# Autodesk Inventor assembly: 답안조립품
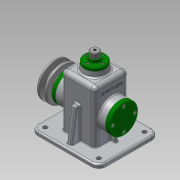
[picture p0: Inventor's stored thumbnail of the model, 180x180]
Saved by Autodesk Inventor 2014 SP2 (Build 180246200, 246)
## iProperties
Created: 2016-08
Part Number: 답안조립품
Document SubType Name: Assembly
Designer: user
Author: user
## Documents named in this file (19)
- C:\Users\user\Desktop\460820V1014\답안조립품.iam
- C:\Users\user\Desktop\460820V1014\본체.ipt
- C:\Users\user\Desktop\460820V1014\뒤커버.ipt
- C:\Users\user\Desktop\460820V1014\앞커버.ipt
- C:\Users\user\Desktop\460820V1014\상부부시.ipt
- C:\Users\user\Desktop\460820V1014\베어링 15 x 35 x 11.ipt
- C:\Users\user\Desktop\460820V1014\편심축.ipt
- C:\Users\user\Desktop\460820V1014\오일실 15 25 7.ipt
- C:\Users\user\Desktop\460820V1014\멈춤링 15 x 1.ipt
- C:\Users\user\Desktop\460820V1014\와셔.ipt
- C:\Users\user\Desktop\460820V1014\링크.ipt
- C:\Users\user\Desktop\460820V1014\슬라이드바.ipt
- C:\Users\user\Desktop\460820V1014\멈춤링 6 x 5.ipt
- C:\Users\user\Desktop\460820V1014\고정핀.ipt
- C:\Users\user\Desktop\460820V1014\키 5 x 5 x 14.ipt
- C:\Users\user\Desktop\460820V1014\V-벨트풀리.ipt
- C:\Users\user\Desktop\460820V1014\볼트 M6 x 12.ipt
- C:\Users\user\Desktop\460820V1014\볼트 M3 x 8.ipt
- C:\Users\user\Desktop\460820V1014\볼트 M4 x 10.ipt
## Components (15 placed, 5 different names)
1. 고정핀:1
2. V-벨트풀리:1 — 각도:1
3. ISO 4018 M6 x 12:1 — 강체:1
4. ISO 4762 M3 x 8:1 — 강체:2
5. ISO 4762 M3 x 8:2
6. ISO 4762 M3 x 8:3
7. ISO 4762 M3 x 8:4
8. ISO 4762 M4 x 10:1 — 강체:3
9. ISO 4762 M4 x 10:2
10. ISO 4762 M4 x 10:3
11. ISO 4762 M4 x 10:4
12. ISO 4762 M4 x 10:5 — 강체:4
13. ISO 4762 M4 x 10:6
14. ISO 4762 M4 x 10:7
15. ISO 4762 M4 x 10:8
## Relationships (5: WeldJoint 4, Angle 1)
- 각도:1 [Angle]: V-벨트풀리:1
- 강체:1 [WeldJoint]: ISO 4018 M6 x 12:1
- 강체:2 [WeldJoint]: ISO 4762 M3 x 8:1
- 강체:3 [WeldJoint]: ISO 4762 M4 x 10:1
- 강체:4 [WeldJoint]: ISO 4762 M4 x 10:5
